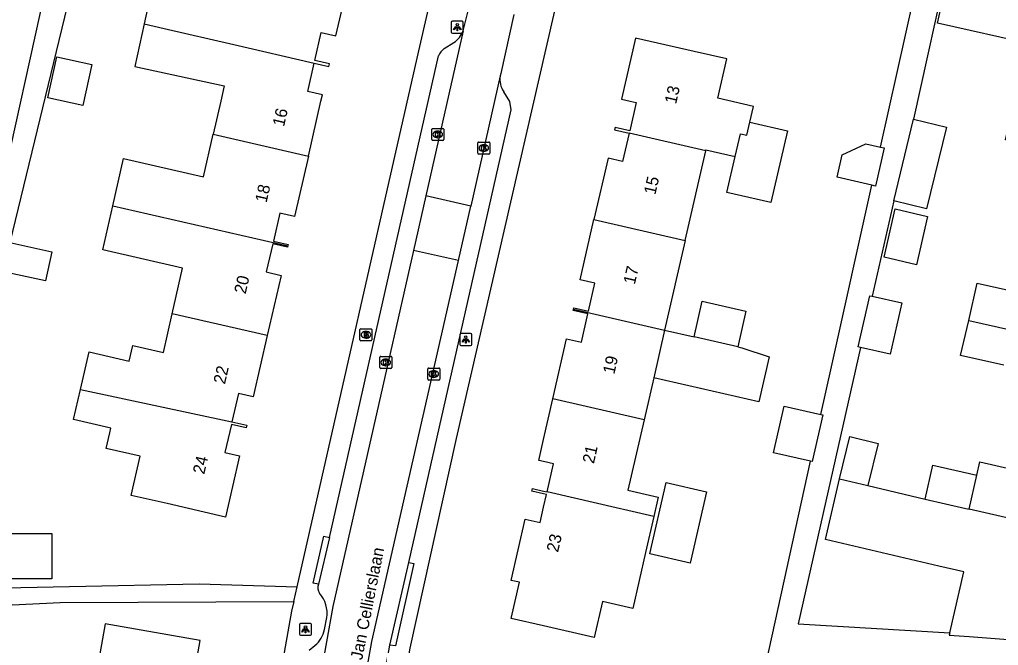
# Model space of a CAD drawing. Extents: x 163686 to 164493, y 382719 to 383870.
# Drawn here: x 163956.3 to 164037.9, y 383454.6 to 383506.8 of the extents above; entities that cross this region are included whole.
import ezdxf

# ---------------------------------------------------------------- set-up
doc = ezdxf.new("R2010")
doc.units = 0
for name, color, linetype in [('IMGEO_Brandkraan', 7, 'Continuous'), ('IMGEO_Kolk', 7, 'Continuous'), ('IMGEO_Lichtpunt', 7, 'Continuous'), ('IMGEO_Openbare_ruimte_label', 7, 'Continuous'), ('IMGEO_Pand', 7, 'Continuous'), ('IMGEO_Pand_nummerreeks', 7, 'Continuous'), ('IMGEO_Rijbaan_lokaal_open', 7, 'Continuous'), ('IMGEO_Voetpad_open', 7, 'Continuous')]:
    doc.layers.add(name, color=color, linetype=linetype)

msp = doc.modelspace()

# ---------------------------------------------------------------- linework, layer by layer
at = {"layer": 'IMGEO_Brandkraan'}
for p, q in [((163984.697, 383480.107), (163984.697, 383480.959)), ((163984.772, 383481.033), (163985.624, 383481.033)), ((163985.185, 383480.813), (163985.21, 383480.813)), ((163985.698, 383480.959), (163985.698, 383480.107)), ((163985.624, 383480.033), (163984.772, 383480.033)), ((163985.208, 383480.253), (163985.183, 383480.253))]:
    msp.add_line(p, q, dxfattribs=at)
for points in [[(163984.697, 383480.107), (163984.697, 383480.959)], [(163984.772, 383481.033), (163985.624, 383481.033)], [(163985.045, 383480.733), (163985.045, 383480.333), (163985.258, 383480.333)], [(163985.276, 383480.733), (163985.045, 383480.733)], [(163985.698, 383480.959), (163985.698, 383480.107)], [(163985.624, 383480.033), (163984.772, 383480.033)], [(163985.224, 383480.652), (163985.17, 383480.652), (163985.17, 383480.576)], [(163985.17, 383480.576), (163985.223, 383480.576)], [(163985.232, 383480.5), (163985.17, 383480.5), (163985.17, 383480.419)], [(163985.17, 383480.419), (163985.232, 383480.419)]]:
    msp.add_lwpolyline(points, dxfattribs=at)
for centre, radius, start, end in [((163984.774, 383480.957), 0.0765, 91.55205, 178.44795), ((163984.774, 383480.957), 0.0765, 91.55205, 178.44795), ((163985.28, 383480.588), 0.145, 59.4692, 91.53667), ((163985.305, 383480.635), 0.0922, 285.51372, 58.15012), ((163985.622, 383480.957), 0.0765, 1.55205, 88.44795), ((163985.622, 383480.957), 0.0765, 1.55205, 88.44795), ((163984.774, 383480.109), 0.0765, 181.55205, 268.44795), ((163984.774, 383480.109), 0.0765, 181.55205, 268.44795), ((163985.225, 383480.614), 0.0379, 267.82845, 90.93552), ((163985.233, 383480.459), 0.0404, 269.87594, 90.50774), ((163985.264, 383480.584), 0.251, 268.66757, 293.53466), ((163985.31, 383480.443), 0.105, 301.31148, 78.98903), ((163985.622, 383480.109), 0.0765, 271.55205, 358.44795), ((163985.622, 383480.109), 0.0765, 271.55205, 358.44795)]:
    msp.add_arc(centre, radius, start, end, dxfattribs=at)
for centre, major_axis, ratio, start_param, end_param in [((163985.184, 383480.533), (-0.387, 0.002), 0.722429, 4.712389, 7.853982), ((163985.209, 383480.533), (-0.39, 0.002), 0.717154, 1.570796, 4.712389)]:
    msp.add_ellipse(centre, major_axis=major_axis, ratio=ratio, start_param=start_param, end_param=end_param, dxfattribs=at)
at = {"layer": 'IMGEO_Kolk'}
for p, q in [((163990.682, 383496.805), (163990.682, 383497.657)), ((163990.757, 383497.731), (163991.609, 383497.731)), ((163991.17, 383497.511), (163991.195, 383497.511)), ((163991.683, 383497.657), (163991.683, 383496.805)), ((163991.609, 383496.731), (163990.757, 383496.731)), ((163991.193, 383496.951), (163991.168, 383496.951)), ((163994.52, 383495.669), (163994.52, 383496.521)), ((163994.595, 383496.595), (163995.447, 383496.595)), ((163995.008, 383496.375), (163995.033, 383496.375)), ((163995.521, 383496.521), (163995.521, 383495.669)), ((163995.447, 383495.595), (163994.595, 383495.595)), ((163995.031, 383495.815), (163995.006, 383495.815)), ((163986.354, 383477.806), (163986.354, 383478.658)), ((163986.429, 383478.732), (163987.281, 383478.732)), ((163986.842, 383478.512), (163986.867, 383478.512)), ((163987.355, 383478.658), (163987.355, 383477.806)), ((163987.281, 383477.732), (163986.429, 383477.732)), ((163986.865, 383477.952), (163986.84, 383477.952)), ((163990.354, 383476.835), (163990.354, 383477.687)), ((163990.429, 383477.761), (163991.281, 383477.761)), ((163990.842, 383477.541), (163990.867, 383477.541)), ((163991.355, 383477.687), (163991.355, 383476.835)), ((163991.281, 383476.761), (163990.429, 383476.761)), ((163990.865, 383476.981), (163990.84, 383476.981))]:
    msp.add_line(p, q, dxfattribs=at)
for points in [[(163990.682, 383496.805), (163990.682, 383497.657)], [(163990.757, 383497.731), (163991.609, 383497.731)], [(163991.003, 383497.431), (163991.126, 383497.431), (163991.126, 383497.28), (163991.256, 383497.431), (163991.42, 383497.431), (163991.274, 383497.28), (163991.427, 383497.031), (163991.275, 383497.031), (163991.19, 383497.195), (163991.126, 383497.128), (163991.126, 383497.031), (163991.003, 383497.031), (163991.003, 383497.431)], [(163991.683, 383497.657), (163991.683, 383496.805)], [(163991.609, 383496.731), (163990.757, 383496.731)], [(163994.52, 383495.669), (163994.52, 383496.521)], [(163994.595, 383496.595), (163995.447, 383496.595)], [(163994.841, 383496.295), (163994.964, 383496.295), (163994.964, 383496.144), (163995.094, 383496.295), (163995.258, 383496.295), (163995.112, 383496.144), (163995.265, 383495.895), (163995.113, 383495.895), (163995.028, 383496.059), (163994.964, 383495.992), (163994.964, 383495.895), (163994.841, 383495.895), (163994.841, 383496.295)], [(163995.521, 383496.521), (163995.521, 383495.669)], [(163995.447, 383495.595), (163994.595, 383495.595)], [(163986.354, 383477.806), (163986.354, 383478.658)], [(163986.429, 383478.732), (163987.281, 383478.732)], [(163986.675, 383478.432), (163986.798, 383478.432), (163986.798, 383478.281), (163986.928, 383478.432), (163987.092, 383478.432), (163986.946, 383478.281), (163987.099, 383478.032), (163986.947, 383478.032), (163986.862, 383478.196), (163986.798, 383478.129), (163986.798, 383478.032), (163986.675, 383478.032), (163986.675, 383478.432)], [(163987.355, 383478.658), (163987.355, 383477.806)], [(163987.281, 383477.732), (163986.429, 383477.732)], [(163990.354, 383476.835), (163990.354, 383477.687)], [(163990.429, 383477.761), (163991.281, 383477.761)], [(163990.675, 383477.461), (163990.798, 383477.461), (163990.798, 383477.31), (163990.928, 383477.461), (163991.092, 383477.461), (163990.946, 383477.31), (163991.099, 383477.061), (163990.947, 383477.061), (163990.862, 383477.225), (163990.798, 383477.158), (163990.798, 383477.061), (163990.675, 383477.061), (163990.675, 383477.461)], [(163991.355, 383477.687), (163991.355, 383476.835)], [(163991.281, 383476.761), (163990.429, 383476.761)]]:
    msp.add_lwpolyline(points, dxfattribs=at)
for centre, start, end in [((163990.759, 383497.655), 91.55205, 178.44795), ((163990.759, 383497.655), 91.55205, 178.44795), ((163991.607, 383497.655), 1.55205, 88.44795), ((163991.607, 383497.655), 1.55205, 88.44795), ((163990.759, 383496.807), 181.55205, 268.44795), ((163990.759, 383496.807), 181.55205, 268.44795), ((163991.607, 383496.807), 271.55205, 358.44795), ((163991.607, 383496.807), 271.55205, 358.44795), ((163994.597, 383496.519), 91.55205, 178.44795), ((163994.597, 383496.519), 91.55205, 178.44795), ((163995.445, 383496.519), 1.55205, 88.44795), ((163995.445, 383496.519), 1.55205, 88.44795), ((163994.597, 383495.671), 181.55205, 268.44795), ((163994.597, 383495.671), 181.55205, 268.44795), ((163995.445, 383495.671), 271.55205, 358.44795), ((163995.445, 383495.671), 271.55205, 358.44795), ((163986.431, 383478.656), 91.55205, 178.44795), ((163986.431, 383478.656), 91.55205, 178.44795), ((163987.279, 383478.656), 1.55205, 88.44795), ((163987.279, 383478.656), 1.55205, 88.44795), ((163986.431, 383477.808), 181.55205, 268.44795), ((163986.431, 383477.808), 181.55205, 268.44795), ((163987.279, 383477.808), 271.55205, 358.44795), ((163987.279, 383477.808), 271.55205, 358.44795), ((163990.431, 383477.685), 91.55205, 178.44795), ((163990.431, 383477.685), 91.55205, 178.44795), ((163991.279, 383477.685), 1.55205, 88.44795), ((163991.279, 383477.685), 1.55205, 88.44795), ((163990.431, 383476.837), 181.55205, 268.44795), ((163990.431, 383476.837), 181.55205, 268.44795), ((163991.279, 383476.837), 271.55205, 358.44795), ((163991.279, 383476.837), 271.55205, 358.44795)]:
    msp.add_arc(centre, 0.0765, start, end, dxfattribs=at)
for centre, major_axis, ratio, start_param, end_param in [((163991.169, 383497.231), (-0.387, 0.002), 0.722429, 4.712389, 7.853982), ((163991.194, 383497.231), (-0.39, 0.002), 0.717154, 1.570796, 4.712389), ((163995.007, 383496.095), (-0.387, 0.002), 0.722429, 4.712389, 7.853982), ((163995.032, 383496.095), (-0.39, 0.002), 0.717154, 1.570796, 4.712389), ((163986.841, 383478.232), (-0.387, 0.002), 0.722429, 4.712389, 7.853982), ((163986.866, 383478.232), (-0.39, 0.002), 0.717154, 1.570796, 4.712389), ((163990.841, 383477.261), (-0.387, 0.002), 0.722429, 4.712389, 7.853982), ((163990.866, 383477.261), (-0.39, 0.002), 0.717154, 1.570796, 4.712389)]:
    msp.add_ellipse(centre, major_axis=major_axis, ratio=ratio, start_param=start_param, end_param=end_param, dxfattribs=at)
at = {"layer": 'IMGEO_Lichtpunt'}
for p, q in [((163992.312, 383506.572), (163992.312, 383505.765)), ((163992.312, 383506.572), (163992.312, 383505.765)), ((163993.214, 383506.667), (163992.406, 383506.667)), ((163993.214, 383506.667), (163992.406, 383506.667)), ((163993.308, 383505.765), (163993.308, 383506.572)), ((163993.308, 383505.765), (163993.308, 383506.572)), ((163992.406, 383505.671), (163993.214, 383505.671)), ((163992.406, 383505.671), (163993.214, 383505.671)), ((163993.017, 383480.536), (163993.017, 383479.729)), ((163993.017, 383480.536), (163993.017, 383479.729)), ((163993.919, 383480.631), (163993.111, 383480.631)), ((163993.919, 383480.631), (163993.111, 383480.631)), ((163994.013, 383479.729), (163994.013, 383480.536)), ((163994.013, 383479.729), (163994.013, 383480.536)), ((163993.111, 383479.635), (163993.919, 383479.635)), ((163993.111, 383479.635), (163993.919, 383479.635)), ((163979.665, 383456.385), (163979.665, 383455.578)), ((163979.665, 383456.385), (163979.665, 383455.578)), ((163980.567, 383456.48), (163979.759, 383456.48)), ((163980.567, 383456.48), (163979.759, 383456.48)), ((163980.661, 383455.578), (163980.661, 383456.385)), ((163980.661, 383455.578), (163980.661, 383456.385)), ((163979.759, 383455.484), (163980.567, 383455.484)), ((163979.759, 383455.484), (163980.567, 383455.484))]:
    msp.add_line(p, q, dxfattribs=at)
for points in [[(163992.686, 383506.236), (163992.725, 383506.208), (163992.537, 383505.946), (163992.499, 383505.973), (163992.686, 383506.236)], [(163992.788, 383506.188), (163992.835, 383506.188), (163992.835, 383505.866), (163992.788, 383505.866), (163992.788, 383506.188)], [(163992.898, 383506.208), (163992.936, 383506.235), (163993.123, 383505.973), (163993.084, 383505.945), (163992.898, 383506.208)], [(163993.391, 383480.2), (163993.43, 383480.172), (163993.242, 383479.91), (163993.204, 383479.937), (163993.391, 383480.2)], [(163993.493, 383480.152), (163993.54, 383480.152), (163993.54, 383479.83), (163993.493, 383479.83), (163993.493, 383480.152)], [(163993.603, 383480.172), (163993.641, 383480.199), (163993.828, 383479.937), (163993.789, 383479.909), (163993.603, 383480.172)], [(163980.039, 383456.049), (163980.078, 383456.021), (163979.89, 383455.759), (163979.852, 383455.786), (163980.039, 383456.049)], [(163980.141, 383456.001), (163980.188, 383456.001), (163980.188, 383455.679), (163980.141, 383455.679), (163980.141, 383456.001)], [(163980.251, 383456.021), (163980.289, 383456.048), (163980.476, 383455.786), (163980.437, 383455.758), (163980.251, 383456.021)]]:
    msp.add_lwpolyline(points, dxfattribs=at)
for centre in [(163992.811, 383506.37), (163993.516, 383480.334), (163980.164, 383456.183)]:
    msp.add_circle(centre, 0.0994, dxfattribs=at)
for centre, start, end in [((163992.406, 383506.572), 90, 180), ((163992.406, 383506.572), 90, 180), ((163993.214, 383506.572), 0, 90), ((163993.214, 383506.572), 0, 90), ((163992.406, 383505.765), 180, 270), ((163992.406, 383505.765), 180, 270), ((163993.214, 383505.765), 270, 0), ((163993.214, 383505.765), 270, 360), ((163993.111, 383480.536), 90, 180), ((163993.111, 383480.536), 90, 180), ((163993.919, 383480.536), 0, 90), ((163993.919, 383480.536), 0, 90), ((163993.111, 383479.729), 180, 270), ((163993.111, 383479.729), 180, 270), ((163993.919, 383479.729), 270, 0), ((163993.919, 383479.729), 270, 360), ((163979.759, 383456.385), 90, 180), ((163979.759, 383456.385), 90, 180), ((163980.567, 383456.385), 0, 90), ((163980.567, 383456.385), 0, 90), ((163979.759, 383455.578), 180, 270), ((163979.759, 383455.578), 180, 270), ((163980.567, 383455.578), 270, 0), ((163980.567, 383455.578), 270, 360)]:
    msp.add_arc(centre, 0.0946, start, end, dxfattribs=at)
at = {"layer": 'IMGEO_Pand'}
for points in [[(163980.89, 383503.171), (163982.117, 383502.886), (163982.166, 383503.1), (163980.938, 383503.382), (163981.477, 383505.731), (163982.704, 383505.449), (163983.874, 383510.549), (163979.002, 383511.67), (163975.999, 383512.34), (163974.763, 383512.616), (163973.576, 383511.949), (163972.759, 383508.421), (163969.125, 383509.257), (163967.425, 383509.669), (163966.723, 383506.437)], [(164042.291, 383495.9), (164038.483, 383496.766), (164039.487, 383501.181), (164045.932, 383499.715), (164045.997, 383500), (164046.662, 383502.927), (164040.647, 383504.295), (164040.727, 383504.716), (164032.829, 383506.5), (164033.806, 383510.81), (164044.764, 383508.37), (164049.644, 383507.284), (164049.387, 383506.153), (164054.798, 383504.922), (164053.966, 383501.265), (164054.141, 383501.225), (164053.863, 383500), (164052.988, 383496.145), (164051.866, 383496.4), (164051.33, 383494.04), (164052.451, 383493.785), (164052.409, 383493.6)], [(163966.723, 383506.437), (163965.951, 383502.885), (163973.39, 383501.269), (163973.103, 383500), (163972.474, 383497.244)], [(163966.723, 383506.437), (163968.389, 383506.055), (163974.181, 383504.727), (163980.89, 383503.171)], [(164017.185, 383498.249), (164017.486, 383499.562), (164014.516, 383500.243), (164015.267, 383503.522), (164012.537, 383504.146), (164007.662, 383505.261), (164006.495, 383500.164), (164007.212, 383500), (164007.714, 383499.885), (164007.176, 383497.536), (164005.957, 383497.814), (164005.907, 383497.599), (164007.126, 383497.323)], [(163958.684, 383500.292), (163959.439, 383503.709), (163962.368, 383503.063), (163961.614, 383499.645), (163958.684, 383500.292)], [(163980.406, 383495.425), (163981.455, 383500), (163981.578, 383500.537), (163980.35, 383500.819), (163980.89, 383503.171)], [(164017.185, 383498.249), (164020.318, 383497.53), (164018.945, 383491.544), (164015.279, 383492.385), (164015.968, 383495.391)], [(164015.968, 383495.391), (164016.401, 383497.279), (164016.935, 383497.156), (164017.185, 383498.249)], [(164030.829, 383498.491), (164033.562, 383497.825), (164031.905, 383491.026), (164029.172, 383491.692)], [(164029.172, 383491.692), (164030.829, 383498.491)], [(163964.108, 383491.289), (163965.006, 383495.225), (163971.664, 383493.697), (163972.474, 383497.244)], [(163972.474, 383497.244), (163980.406, 383495.425)], [(164007.126, 383497.323), (164006.588, 383494.971), (164005.37, 383495.249), (164004.201, 383490.138)], [(164013.514, 383495.875), (164007.126, 383497.323)], [(164027.36, 383492.998), (164024.464, 383493.659), (164024.888, 383495.52), (164026.852, 383496.453), (164028.068, 383496.176)], [(163980.406, 383495.425), (163979.254, 383490.399), (163978.025, 383490.681), (163977.487, 383488.332), (163978.715, 383488.05), (163978.691, 383487.945)], [(164011.801, 383488.399), (164013.514, 383495.875)], [(164013.514, 383495.875), (164013.531, 383495.949), (164015.968, 383495.391)], [(164028.068, 383496.176), (164028.378, 383496.105), (164027.653, 383492.931), (164027.36, 383492.998)], [(163969.058, 383482.279), (163969.924, 383486.074), (163963.266, 383487.602), (163964.108, 383491.289)], [(163964.108, 383491.289), (163978.691, 383487.945)], [(164031.084, 383486.371), (164028.372, 383486.988), (164029.287, 383491.016), (164032, 383490.399), (164031.084, 383486.371)], [(164002.488, 383482.663), (164002.514, 383482.774), (164003.732, 383482.496), (164004.268, 383484.835), (164003.051, 383485.114), (164004.201, 383490.138)], [(164004.201, 383490.138), (164011.801, 383488.399)], [(163955.524, 383488.221), (163959.03, 383487.452), (163958.497, 383485.022), (163954.991, 383485.791)], [(163978.691, 383487.945), (163978.666, 383487.835), (163977.437, 383488.117), (163976.899, 383485.768), (163978.126, 383485.486), (163976.973, 383480.464)], [(164011.801, 383488.399), (164010.087, 383480.924)], [(164035.418, 383481.73), (164036.134, 383484.847), (164039.728, 383484.021), (164039.612, 383483.517)], [(164012.536, 383480.363), (164013.218, 383483.345), (164016.856, 383482.512), (164016.173, 383479.531)], [(164026.418, 383479.475), (164026.224, 383479.519), (164027.195, 383483.791), (164027.381, 383483.749)], [(164027.381, 383483.749), (164029.863, 383483.185), (164028.891, 383478.913), (164026.418, 383479.475)], [(164000.776, 383475.186), (164001.923, 383480.2), (164003.152, 383479.92), (164003.691, 383482.278), (164002.464, 383482.559), (164002.488, 383482.663)], [(164002.488, 383482.663), (164010.087, 383480.924)], [(163961.425, 383475.984), (163962.144, 383479.11), (163965.476, 383478.343), (163965.775, 383479.643), (163968.323, 383479.056), (163969.058, 383482.279)], [(163976.973, 383480.464), (163969.058, 383482.279)], [(164038.342, 383477.986), (164034.748, 383478.812), (164035.418, 383481.73)], [(164035.418, 383481.73), (164039.014, 383480.913)], [(164010.087, 383480.924), (164009.177, 383476.953)], [(164010.087, 383480.924), (164012.536, 383480.363)], [(163976.973, 383480.464), (163975.802, 383475.349), (163974.575, 383475.631), (163974.032, 383473.265)], [(164016.173, 383479.531), (164012.536, 383480.363)], [(164016.173, 383479.531), (164016.531, 383479.449), (164018.795, 383478.688), (164017.939, 383474.948), (164009.177, 383476.953)], [(164009.177, 383476.953), (164008.374, 383473.447)], [(163974.032, 383473.265), (163975.263, 383473), (163975.214, 383472.785), (163973.987, 383473.067), (163973.448, 383470.718), (163974.677, 383470.436), (163973.507, 383465.338), (163968.635, 383466.459), (163965.631, 383467.15), (163966.38, 383470.407), (163963.56, 383471.058), (163963.857, 383472.352), (163963.947, 383472.743), (163960.843, 383473.458), (163961.425, 383475.984)], [(163961.425, 383475.984), (163974.032, 383473.265)], [(164000.29, 383467.429), (164000.828, 383469.785), (164000, 383469.975), (163999.604, 383470.066), (164000, 383471.797), (164000.776, 383475.186)], [(164008.374, 383473.447), (164000.776, 383475.186)], [(164022.253, 383469.996), (164019.156, 383470.705), (164020.044, 383474.582), (164023.11, 383473.879)], [(164008.374, 383473.447), (164007.027, 383467.574), (164009.561, 383466.993), (164009.194, 383465.391)], [(164023.11, 383473.879), (164023.255, 383473.846), (164022.367, 383469.97), (164022.253, 383469.996)], [(164036.102, 383468.827), (164036.356, 383469.943), (164039.025, 383469.336), (164039.827, 383472.862)], [(164024.666, 383468.532), (164025.509, 383472.047), (164027.867, 383471.482), (164027.024, 383467.966)], [(164031.787, 383466.824), (164032.432, 383469.661), (164036.102, 383468.827)], [(164033.838, 383455.681), (164035.026, 383460.761), (164032.923, 383461.253), (164023.48, 383463.462), (164024.666, 383468.532)], [(164024.666, 383468.532), (164027.024, 383467.966)], [(164035.457, 383465.99), (164036.102, 383468.827)], [(164009.194, 383465.391), (164008.505, 383462.386), (164007.438, 383457.729), (164004.904, 383458.31), (164004.217, 383455.314), (164000, 383456.279), (163997.306, 383456.896), (163997.995, 383459.908), (163997.313, 383460.064), (163998.48, 383465.161), (163999.708, 383464.881), (164000, 383466.159), (164000.243, 383467.221), (164000, 383467.276), (163999.015, 383467.501), (163999.065, 383467.716), (164000, 383467.503), (164000.29, 383467.429)], [(164013.583, 383467.45), (164012.224, 383461.496), (164008.849, 383462.267), (164010.209, 383468.22), (164013.583, 383467.45)], [(164027.024, 383467.966), (164031.787, 383466.824)], [(164009.194, 383465.391), (164006.66, 383465.971), (164006.406, 383466.029), (164000.29, 383467.429)], [(164031.787, 383466.824), (164035.193, 383466.05), (164035.457, 383465.99)], [(164045.601, 383463.636), (164038.127, 383465.384), (164035.457, 383465.99)], [(163959.021, 383463.968), (163959.021, 383460.196), (163952.982, 383460.196), (163952.982, 383463.968), (163959.021, 383463.968)], [(163971.222, 383442.399), (163971.241, 383442.507), (163970.002, 383442.726), (163970.419, 383445.1), (163971.658, 383444.881), (163972.552, 383449.968), (163970.563, 383450.318), (163971.394, 383455.046), (163966.47, 383455.912), (163963.466, 383456.44), (163962.504, 383450.964), (163964.729, 383450.573), (163964.04, 383446.652), (163957.86, 383447.737), (163957.344, 383444.803)], [(164033.838, 383455.681), (164033.797, 383455.507), (164035.466, 383455.379), (164041.615, 383454.909), (164041.601, 383455.215)]]:
    msp.add_lwpolyline(points, dxfattribs=at)
at = {"layer": 'IMGEO_Rijbaan_lokaal_open'}
for points in [[(163993.3, 383505.876), (163993.853, 383508.085)], [(163997.525, 383507.217), (163996.435, 383502.317), (163996.386, 383502.1)], [(163993.3, 383505.876), (163990.186, 383492.109)], [(163996.386, 383502.1), (163993.929, 383491.262)], [(163990.186, 383492.109), (163989.158, 383487.564)], [(163993.929, 383491.262), (163990.186, 383492.109)], [(163992.899, 383486.716), (163993.929, 383491.262)], [(163989.158, 383487.564), (163982.448, 383457.894), (163974.001, 383410.775)], [(163992.899, 383486.716), (163989.158, 383487.564)], [(163977.283, 383407.759), (163985.704, 383454.97), (163992.899, 383486.716)]]:
    msp.add_lwpolyline(points, dxfattribs=at)
at = {"layer": 'IMGEO_Voetpad_open'}
for points in [[(163917.615, 383461.091), (163931.28, 383458.387), (163947.659, 383458.649), (163947.714, 383459.916), (163952.093, 383479.924), (163953.709, 383487.39), (163955.229, 383494.411), (163963.652, 383532.606), (163969.157, 383557.572), (163957.687, 383560.101)], [(163979.464, 383459.533), (163989.618, 383504.21), (164000.14, 383549.983)], [(164010.179, 383547.596), (164003.126, 383517.221), (163992.708, 383471.874), (163988.857, 383454.418), (163980.269, 383406.063)], [(164028.068, 383496.176), (164032.229, 383514.859), (164038.113, 383541.275), (164028.338, 383543.43)], [(164033.805, 383511.988), (164030.829, 383498.491)], [(163960.306, 383507.908), (163955.524, 383488.221)], [(163991.722, 383504.379), (163992.53, 383504.888)], [(163982.152, 383463.629), (163991.259, 383503.774)], [(163988.771, 383461.562), (163997.311, 383499.267), (163997.186, 383499.984), (163996.681, 383500.787)], [(164023.11, 383473.879), (164023.988, 383477.86), (164027.36, 383492.998)], [(164029.172, 383491.692), (164027.381, 383483.749)], [(163954.991, 383485.791), (163949.665, 383459.33), (163971.316, 383459.761), (163979.464, 383459.533)], [(164026.418, 383479.475), (164021.225, 383456.438), (164033.838, 383455.681)], [(164018.288, 383452.025), (164022.253, 383469.996)], [(163981.242, 383459.738), (163980.807, 383459.836), (163981.694, 383463.752), (163982.152, 383463.629)], [(163982.152, 383463.629), (163981.242, 383459.738)], [(163987.196, 383454.676), (163988.771, 383461.562)], [(163988.771, 383461.562), (163989.194, 383461.47), (163987.676, 383454.596), (163987.196, 383454.676)], [(163917.296, 383459.667), (163935.036, 383456.499), (163935.139, 383457.026), (163959.724, 383458.221), (163979.186, 383458.312)], [(163979.186, 383458.312), (163979.464, 383459.533)], [(163979.186, 383458.312), (163978.999, 383457.491), (163971.042, 383412.745), (163970.084, 383408.049)], [(163981.751, 383455.971), (163981.946, 383456.955)], [(163979.344, 383410.226), (163987.196, 383454.676)], [(163980.48, 383454.259), (163980.949, 383454.641)]]:
    msp.add_lwpolyline(points, dxfattribs=at)
for centre, radius, start, end in [((163991.52, 383506.469), 1.876, 302.56964, 341.56807), ((163992.477, 383503.322), 1.299, 125.52305, 159.62407), ((163998.16, 383501.809), 1.798, 170.68661, 214.63886), ((163981.987, 383459.455), 0.797, 159.22204, 215.70627), ((163979.366, 383457.294), 2.603, 352.50851, 40.65737), ((163979.583, 383456.371), 2.204, 308.28219, 349.53723)]:
    msp.add_arc(centre, radius, start, end, dxfattribs=at)

# ---------------------------------------------------------------- texts
at = {"layer": 'IMGEO_Openbare_ruimte_label'}
msp.add_text('Jan Cellierslaan', height=1, rotation=78.81367, dxfattribs=at).set_placement((163984.88, 383453.372))
at = {"layer": 'IMGEO_Pand_nummerreeks'}
for s, rotation, p in [('13', 77.0972, (164011.039, 383499.709)), ('16', 77.08574, (163978.372, 383497.828)), ('18', 77.08574, (163976.916, 383491.485)), ('15', 77.13158, (164009.309, 383492.151)), ('17', 77.13226, (164007.601, 383484.673)), ('20', 77.08574, (163975.173, 383483.883)), ('19', 77.13158, (164005.893, 383477.196)), ('22', 77.08574, (163973.45, 383476.364)), ('21', 77.13158, (164004.19, 383469.74)), ('24', 77.08574, (163971.727, 383468.853)), ('23', 77.11439, (164001.202, 383462.35))]:
    msp.add_text(s, height=1, rotation=rotation, dxfattribs=at).set_placement(p)

doc.saveas('drawing.dxf')
